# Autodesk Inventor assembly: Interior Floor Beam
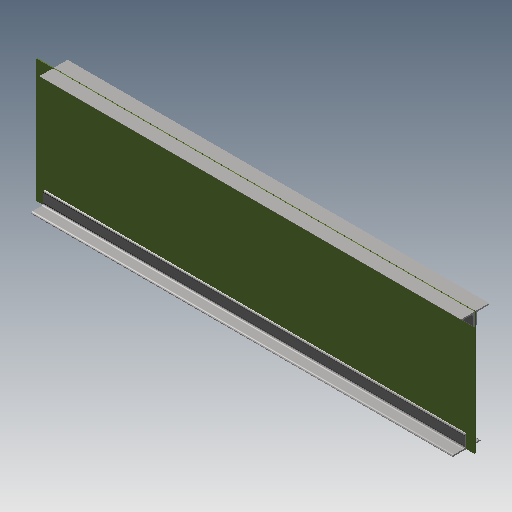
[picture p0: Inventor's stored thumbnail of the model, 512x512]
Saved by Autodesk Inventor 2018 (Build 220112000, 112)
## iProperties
Created: 2018-02
Part Number: Interior Floor Beam
Document SubType Name: Assembly
Designer: STK
Author: STK
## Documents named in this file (6)
- D:\SolidWorks\Through Truss\Interior Floor Beam\Interior Floor Beam.iam
- D:\SolidWorks\Through Truss\Floor Beam_End\Web_FB_end\Web_FB_Interior.ipt
- D:\SolidWorks\Through Truss\Floor Beam_End\Web_FB_end.ipt
- D:\SolidWorks\Through Truss\Floor Beam_End\Top Flange Angle_FB_End\Top Flange Angle_FB_Interior.ipt
- D:\SolidWorks\Through Truss\Floor Beam_End\Top Flange Angle_FB_End.ipt
- D:\SolidWorks\Through Truss\Floor Beam_End\Top Flange Angle_FB_End\Top Flange Angle_FB_End-01.ipt
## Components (5 placed, 3 different names)
1. Web_FB_Interior:1 — Mate:1, Flush:1, Mate:2, Mate:3, Flush:2, Flush:7, Flush:8, Mate:4, Flush:9
2. Top Flange Angle_FB_Interior:1 — Mate:3, Flush:2, Flush:7
3. Top Flange Angle_FB_Interior:3
4. Top Flange Angle_FB_End-01:4 — Flush:8, Mate:4, Flush:9
5. Top Flange Angle_FB_End-01:5
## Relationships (9: Flush 5, Mate 4)
- Mate:1: Web_FB_Interior:1
- Flush:1: Web_FB_Interior:1
- Mate:2: Web_FB_Interior:1
- Mate:3: Web_FB_Interior:1 ↔ Top Flange Angle_FB_Interior:1
- Flush:2: Web_FB_Interior:1 ↔ Top Flange Angle_FB_Interior:1
- Flush:7: Web_FB_Interior:1 ↔ Top Flange Angle_FB_Interior:1
- Flush:8: Web_FB_Interior:1 ↔ Top Flange Angle_FB_End-01:4
- Mate:4: Web_FB_Interior:1 ↔ Top Flange Angle_FB_End-01:4
- Flush:9: Web_FB_Interior:1 ↔ Top Flange Angle_FB_End-01:4
